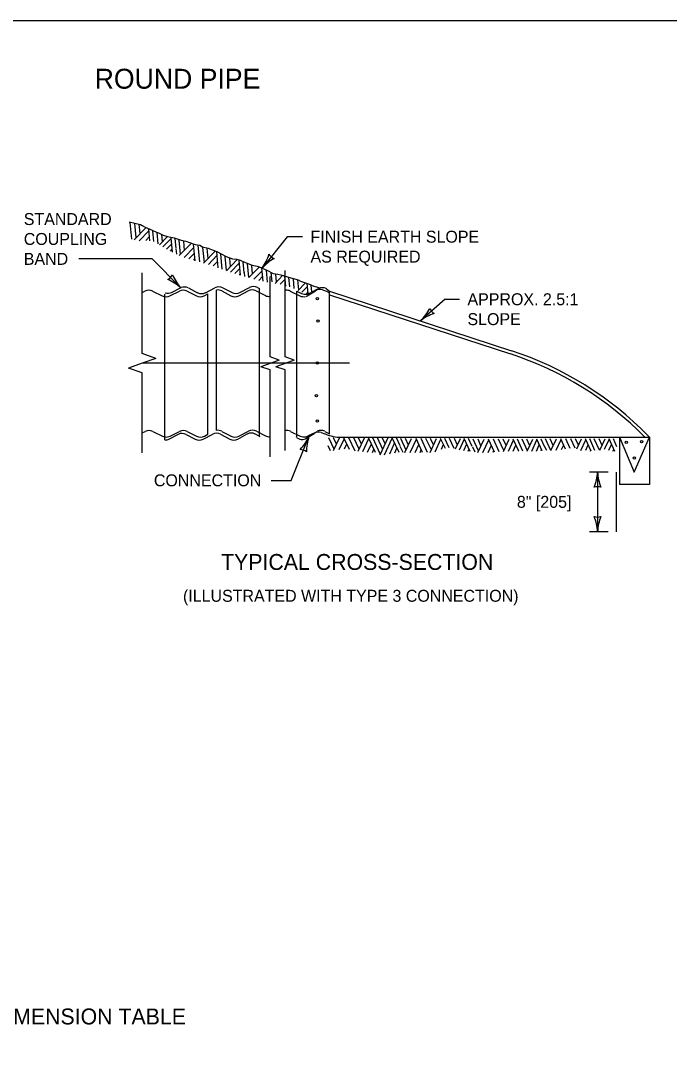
# Model space of a CAD drawing. Extents: x 49991.4 to 50021, y 49987.6 to 50011.4.
# Drawn here: x 50010.14 to 50013.4, y 49993.85 to 49999 of the extents above; entities that cross this region are included whole.
import ezdxf

# ---------------------------------------------------------------- set-up
doc = ezdxf.new("R2010")
doc.units = 0
for name, color, linetype in [('Level 1', 7, 'Continuous'), ('Level 2', 7, 'Continuous'), ('Level 3', 7, 'Continuous'), ('Level 4', 7, 'Continuous'), ('Level 5', 7, 'Continuous'), ('Level 6', 7, 'Continuous')]:
    doc.layers.add(name, color=color, linetype=linetype)

msp = doc.modelspace()

# ---------------------------------------------------------------- linework, layer by layer
at = {"layer": 'Level 1'}
for p, q in [((50010.7033, 49997.9015), (50010.6957, 49997.9852)), ((50010.7251, 49997.9089), (50010.719, 49997.9791)), ((50010.7446, 49997.9285), (50010.7405, 49997.9755)), ((50010.7149, 49997.8973), (50010.7753, 49997.9596)), ((50010.7405, 49997.8927), (50010.7891, 49997.9422)), ((50010.7744, 49997.8948), (50010.792, 49997.9137)), ((50010.7941, 49997.8916), (50010.7884, 49997.9522)), ((50010.8138, 49997.8885), (50010.8089, 49997.9428)), ((50010.836, 49997.8769), (50010.8307, 49997.9338)), ((50010.8418, 49997.8726), (50010.8826, 49997.9144)), ((50010.857, 49997.8886), (50010.854, 49997.9245)), ((50010.8583, 49997.8617), (50010.9006, 49997.9049)), ((50010.8782, 49997.8509), (50010.9038, 49997.8774)), ((50010.9076, 49997.836), (50010.9004, 49997.9079)), ((50010.9253, 49997.8561), (50010.9207, 49997.9036)), ((50010.9483, 49997.825), (50010.941, 49997.8963)), ((50010.9418, 49997.8181), (50011.0016, 49997.8796)), ((50010.9674, 49997.8444), (50010.9638, 49997.8906)), ((50010.9658, 49997.8093), (50011.0149, 49997.8594)), ((50011.0213, 49997.7925), (50011.0128, 49997.8759)), ((50011.0446, 49997.7863), (50011.0364, 49997.8694)), ((50011.0676, 49997.7839), (50011.0604, 49997.8587)), ((50010.8977, 49997.8413), (50010.9058, 49997.8503)), ((50010.9286, 49997.825), (50010.9262, 49997.852)), ((50010.9895, 49997.8013), (50011.0178, 49997.8299)), ((50011.064, 49997.7808), (50011.1226, 49997.8403)), ((50011.0867, 49997.8043), (50011.0821, 49997.8532)), ((50011.0876, 49997.7736), (50011.1308, 49997.8179)), ((50011.1372, 49997.7572), (50011.1294, 49997.8375)), ((50011.1572, 49997.7503), (50011.1498, 49997.8255)), ((50011.1792, 49997.7428), (50011.1721, 49997.8138)), ((50011.0141, 49997.7947), (50011.0202, 49997.8013)), ((50011.1121, 49997.7661), (50011.1341, 49997.789)), ((50011.1359, 49997.7578), (50011.1373, 49997.7595)), ((50011.1787, 49997.7425), (50011.2325, 49997.798)), ((50011.1995, 49997.7637), (50011.1953, 49997.8035)), ((50011.1991, 49997.7353), (50011.2428, 49997.7805)), ((50011.2487, 49997.7194), (50011.242, 49997.794)), ((50011.267, 49997.732), (50011.2625, 49997.7866)), ((50011.2909, 49997.7074), (50011.2838, 49997.7785)), ((50011.2909, 49997.7074), (50011.342, 49997.7601)), ((50011.3101, 49997.7274), (50011.3065, 49997.7688)), ((50011.3623, 49997.6897), (50011.3559, 49997.7557)), ((50011.2211, 49997.7278), (50011.2451, 49997.7529)), ((50011.244, 49997.7206), (50011.2478, 49997.7256)), ((50011.2711, 49997.7129), (50011.269, 49997.7334)), ((50011.3167, 49997.6999), (50011.3573, 49997.7417)), ((50011.3419, 49997.6939), (50011.3603, 49997.7125)), ((50011.3855, 49997.6852), (50011.3797, 49997.7447)), ((50011.4082, 49997.6865), (50011.4035, 49997.7333)), ((50011.4227, 49997.6787), (50011.4602, 49997.7178)), ((50011.4292, 49997.6865), (50011.4257, 49997.7247)), ((50011.4773, 49997.6655), (50011.4721, 49997.7145)), ((50011.497, 49997.6606), (50011.4924, 49997.7076)), ((50010.903, 49997.6337), (50010.9508, 49997.6572)), ((50010.9871, 49997.6555), (50011.0336, 49997.6319)), ((50011.0728, 49997.6319), (50011.1206, 49997.6567)), ((50011.1602, 49997.6565), (50011.2064, 49997.6324)), ((50011.2464, 49997.6324), (50011.2942, 49997.6575)), ((50011.3344, 49997.6575), (50011.3441, 49997.6524)), ((50011.448, 49997.6739), (50011.4738, 49997.7001)), ((50011.5193, 49997.6527), (50011.5145, 49997.7017)), ((50011.5417, 49997.6462), (50011.5373, 49997.6968)), ((50011.5385, 49997.6429), (50011.5746, 49997.6803)), ((50011.5579, 49997.6347), (50011.5854, 49997.6629)), ((50011.5884, 49997.6296), (50011.5842, 49997.6776)), ((50011.6075, 49997.6387), (50011.6046, 49997.6685)), ((50011.605, 49997.6345), (50011.6407, 49997.6524)), ((50011.6304, 49997.6613), (50011.6437, 49997.656)), ((50011.6797, 49997.6524), (50011.6965, 49997.639)), ((50010.7546, 49997.6324), (50010.7692, 49997.6396)), ((50010.8079, 49997.6399), (50010.8564, 49997.6158)), ((50010.8943, 49997.6158), (50010.9422, 49997.6396)), ((50010.9814, 49997.6395), (50011.0273, 49997.6158)), ((50011.0668, 49997.6158), (50011.0852, 49997.6255)), ((50011.0852, 49996.9207), (50011.0852, 49997.6255)), ((50011.1284, 49996.9403), (50011.1284, 49997.6451)), ((50011.1545, 49997.6408), (50011.2007, 49997.6164)), ((50011.2406, 49997.6164), (50011.2883, 49997.6416)), ((50011.3282, 49997.6416), (50011.374, 49997.6176)), ((50011.4785, 49997.6449), (50011.4726, 49997.6439)), ((50011.4989, 49997.6402), (50011.5469, 49997.6162)), ((50011.5321, 49996.9041), (50011.5321, 49997.6395)), ((50011.5321, 49997.6395), (50011.5547, 49997.6284)), ((50011.5813, 49997.6285), (50011.588, 49997.6353)), ((50011.5842, 49997.6158), (50011.6262, 49997.642)), ((50011.5931, 49997.6284), (50011.6045, 49997.6337)), ((50011.6603, 49997.6467), (50011.6804, 49997.639)), ((50011.6804, 49997.639), (50011.6964, 49997.6315)), ((50011.6964, 49997.6393), (50012.6098, 49997.3402)), ((50011.6964, 49997.6219), (50012.6047, 49997.3245)), ((50010.7552, 49996.9277), (50010.77, 49996.9351)), ((50010.809, 49996.9351), (50010.8569, 49996.9111)), ((50010.8956, 49996.9112), (50010.9428, 49996.9351)), ((50010.9819, 49996.9346), (50011.0279, 49996.9111)), ((50011.1557, 49996.9354), (50011.2014, 49996.9115)), ((50011.2415, 49996.9115), (50011.2894, 49996.9367)), ((50011.3291, 49996.9369), (50011.3748, 49996.913)), ((50011.4994, 49996.9354), (50011.5482, 49996.9115)), ((50011.5985, 49996.9175), (50011.634, 49996.9354)), ((50011.6538, 49996.9303), (50011.6734, 49996.9222)), ((50011.6728, 49996.9354), (50011.6965, 49996.9235)), ((50010.8677, 49996.8952), (50010.8691, 49996.8952)), ((50010.889, 49996.8965), (50010.937, 49996.9205)), ((50010.9754, 49996.9201), (50011.022, 49996.8965)), ((50011.0614, 49996.8965), (50011.1096, 49996.9213)), ((50011.0677, 49996.9112), (50011.0852, 49996.9205)), ((50011.1492, 49996.9209), (50011.195, 49996.8967)), ((50011.2352, 49996.8967), (50011.2828, 49996.9221)), ((50011.3228, 49996.9221), (50011.3454, 49996.9103)), ((50011.5302, 49996.9065), (50011.5302, 49996.9072)), ((50011.5321, 49996.9034), (50011.5405, 49996.8993)), ((50011.5774, 49996.8991), (50011.6194, 49996.9252)), ((50011.5862, 49996.9115), (50011.5975, 49996.9171)), ((50011.7193, 49996.8453), (50011.692, 49996.9034)), ((50011.7312, 49996.8705), (50011.7158, 49996.9034)), ((50011.7168, 49996.8395), (50011.7462, 49996.9034)), ((50011.7445, 49996.8436), (50011.7706, 49996.8998)), ((50011.7562, 49996.9063), (50013.3036, 49996.9063)), ((50011.7961, 49996.8448), (50011.7686, 49996.9034)), ((50011.8248, 49996.8364), (50011.7937, 49996.9034)), ((50011.8454, 49996.846), (50011.8189, 49996.9034)), ((50011.8402, 49996.8351), (50011.8721, 49996.9034)), ((50011.8566, 49996.8715), (50011.8417, 49996.9034)), ((50011.8634, 49996.8334), (50011.8939, 49996.8993)), ((50011.9274, 49996.8285), (50011.8922, 49996.9034)), ((50011.9525, 49996.8196), (50011.9134, 49996.9034)), ((50011.9641, 49996.8448), (50011.9369, 49996.9034)), ((50011.9512, 49996.8169), (50011.9915, 49996.904)), ((50011.9765, 49996.8705), (50011.9612, 49996.9034)), ((50011.9729, 49996.8172), (50012.0116, 49996.901)), ((50012.0456, 49996.8285), (50012.0112, 49996.9034)), ((50012.0512, 49996.8633), (50012.0325, 49996.9034)), ((50012.0817, 49996.8413), (50012.0542, 49996.8998)), ((50012.0752, 49996.8285), (50012.1081, 49996.8998)), ((50012.0931, 49996.8667), (50012.078, 49996.8998)), ((50012.1014, 49996.8285), (50012.1327, 49996.8959)), ((50012.1638, 49996.8285), (50012.1308, 49996.8998)), ((50012.1888, 49996.8285), (50012.1558, 49996.8998)), ((50012.2076, 49996.8423), (50012.1807, 49996.8998)), ((50012.2008, 49996.8285), (50012.2341, 49996.8998)), ((50012.2183, 49996.8677), (50012.204, 49996.8998)), ((50012.2269, 49996.8321), (50012.256, 49996.8953)), ((50012.278, 49996.8493), (50012.2542, 49996.8998)), ((50012.2975, 49996.8524), (50012.2754, 49996.8998)), ((50012.3222, 49996.8493), (50012.299, 49996.8998)), ((50012.3382, 49996.8668), (50012.3232, 49996.8998)), ((50012.329, 49996.8472), (50012.3535, 49996.9001)), ((50012.3485, 49996.8423), (50012.3737, 49996.8973)), ((50012.4032, 49996.8344), (50012.3727, 49996.8998)), ((50012.413, 49996.8593), (50012.3943, 49996.8998)), ((50012.4452, 49996.8376), (50012.4181, 49996.8959)), ((50012.441, 49996.8287), (50012.4723, 49996.8959)), ((50012.4568, 49996.8626), (50012.4422, 49996.8959)), ((50012.4669, 49996.8285), (50012.4968, 49996.892)), ((50012.5249, 49996.8313), (50012.4945, 49996.8959)), ((50012.5488, 49996.8331), (50012.5198, 49996.8959)), ((50012.5714, 49996.8385), (50012.5448, 49996.8959)), ((50012.5826, 49996.8638), (50012.5682, 49996.8959)), ((50012.5694, 49996.8344), (50012.5978, 49996.8959)), ((50012.5945, 49996.8352), (50012.6203, 49996.8914)), ((50012.6464, 49996.8362), (50012.6182, 49996.8959)), ((50012.6673, 49996.8362), (50012.6395, 49996.8959)), ((50012.6902, 49996.837), (50012.6632, 49996.8959)), ((50012.7024, 49996.8626), (50012.6874, 49996.8959)), ((50012.6895, 49996.8362), (50012.7172, 49996.8962)), ((50012.7114, 49996.8362), (50012.7375, 49996.8933)), ((50012.7638, 49996.8376), (50012.7368, 49996.8959)), ((50012.7774, 49996.8554), (50012.7586, 49996.8959)), ((50012.8084, 49996.8395), (50012.781, 49996.8976)), ((50012.8201, 49996.8649), (50012.805, 49996.8976)), ((50012.8084, 49996.8395), (50012.8356, 49996.8976)), ((50012.8348, 49996.841), (50012.8594, 49996.8938)), ((50012.8816, 49996.8465), (50012.8579, 49996.8976)), ((50012.9052, 49996.8497), (50012.8827, 49996.8976)), ((50012.93, 49996.8501), (50012.908, 49996.8976)), ((50012.9458, 49996.8657), (50012.9312, 49996.8976)), ((50012.9379, 49996.8477), (50012.9611, 49996.8976)), ((50012.958, 49996.8395), (50012.983, 49996.8935)), ((50013.0105, 49996.8355), (50012.9814, 49996.8976)), ((50013.0294, 49996.8395), (50013.0027, 49996.8976)), ((50013.052, 49996.841), (50013.026, 49996.8976)), ((50013.0657, 49996.8649), (50013.0502, 49996.8976)), ((50013.0542, 49996.841), (50013.0805, 49996.898)), ((50013.0776, 49996.8453), (50013.1008, 49996.8951)), ((50013.1296, 49996.8345), (50013.1, 49996.8976)), ((50013.1399, 49996.8575), (50013.1218, 49996.8976)), ((50013.1527, 49996.9063), (50013.1527, 49996.6689)), ((50013.1527, 49996.9063), (50013.2259, 49996.7309)), ((50013.2259, 49996.7309), (50013.3037, 49996.9063)), ((50013.3036, 49996.9058), (50013.2955, 49996.9142)), ((50013.3037, 49996.9063), (50013.3037, 49996.6689)), ((50011.7013, 49996.8376), (50011.6894, 49996.8633)), ((50011.771, 49996.8476), (50011.783, 49996.8731)), ((50011.7946, 49996.8453), (50011.7955, 49996.8466)), ((50011.8873, 49996.8315), (50011.9066, 49996.8731)), ((50011.9117, 49996.8299), (50011.9191, 49996.8459)), ((50011.999, 49996.8223), (50012.0233, 49996.8758)), ((50012.0247, 49996.8274), (50012.035, 49996.8511)), ((50012.0659, 49996.8285), (50012.0514, 49996.8593)), ((50012.1261, 49996.8285), (50012.1448, 49996.8689)), ((50012.1506, 49996.8285), (50012.157, 49996.843)), ((50012.2578, 49996.8458), (50012.2686, 49996.8689)), ((50012.3708, 49996.8391), (50012.3854, 49996.8719)), ((50012.392, 49996.8361), (50012.3972, 49996.8475)), ((50012.4268, 49996.8307), (50012.4152, 49996.8554)), ((50012.4922, 49996.8287), (50012.5089, 49996.8655)), ((50012.5176, 49996.8307), (50012.521, 49996.8391)), ((50012.6192, 49996.8362), (50012.6326, 49996.8655)), ((50012.6442, 49996.8362), (50012.6452, 49996.838)), ((50012.7352, 49996.8362), (50012.7498, 49996.8683)), ((50012.7586, 49996.8373), (50012.7613, 49996.8434)), ((50012.7872, 49996.8386), (50012.7783, 49996.8575)), ((50012.8609, 49996.8439), (50012.8723, 49996.8674)), ((50012.9828, 49996.8403), (50012.9955, 49996.8674)), ((50013.0067, 49996.8362), (50013.0085, 49996.8403)), ((50013.0992, 49996.8412), (50013.1124, 49996.87)), ((50013.1198, 49996.8355), (50013.1239, 49996.8453)), ((50013.3037, 49996.6689), (50013.1527, 49996.6689))]:
    msp.add_line(p, q, dxfattribs=at)
msp.add_lwpolyline([(49999.3835, 49998.9992), (50016.7501, 49998.9992), (50016.7501, 49987.7988), (49999.3835, 49987.7988)], close=True, dxfattribs=at)
for points in [[(50010.69, 49997.9878), (50010.7467, 49997.9745), (50010.755, 49997.9696), (50010.77, 49997.9613), (50010.7934, 49997.9512), (50010.805, 49997.9464), (50010.8269, 49997.9363), (50010.8368, 49997.9329), (50010.8601, 49997.9212), (50010.8818, 49997.9147), (50010.9152, 49997.908), (50010.9268, 49997.9048), (50010.9518, 49997.8964), (50010.9738, 49997.8899), (50010.9937, 49997.8832), (50011.022, 49997.8748), (50011.0454, 49997.8699), (50011.0587, 49997.8615), (50011.0872, 49997.8549), (50011.1121, 49997.845), (50011.1306, 49997.8383), (50011.1521, 49997.8267), (50011.1772, 49997.8133), (50011.209, 49997.8017), (50011.2304, 49997.8), (50011.2472, 49997.795), (50011.2688, 49997.785), (50011.2771, 49997.7819)], [(50011.2768, 49997.7827), (50011.3083, 49997.771), (50011.3334, 49997.7644), (50011.3435, 49997.761), (50011.3819, 49997.7443), (50011.4134, 49997.7278), (50011.4368, 49997.7244), (50011.4518, 49997.7212), (50011.5019, 49997.7062), (50011.5387, 49997.6961), (50011.5504, 49997.6895), (50011.5903, 49997.6763), (50011.6171, 49997.6647), (50011.6304, 49997.6613)], [(50011.643, 49997.656), (50011.6406, 49997.6581)]]:
    msp.add_lwpolyline(points, dxfattribs=at)
for centre, radius in [((50011.635, 49997.6019), 0.00595), ((50011.6386, 49997.4893), 0.00595), ((50011.635, 49997.2786), 0.00595), ((50011.63, 49997.1146), 0.00595), ((50011.635, 49996.9871), 0.00595), ((50013.1862, 49996.8799), 0.00594), ((50013.2632, 49996.8829), 0.00594), ((50013.2274, 49996.8009), 0.00594)]:
    msp.add_circle(centre, radius, dxfattribs=at)
for centre, radius, start, end in [((50010.9674, 49997.6173), 0.0432, 62.9182, 112.5905), ((50011.1404, 49997.6184), 0.0432, 62.3296, 117.1813), ((50011.3142, 49997.6193), 0.0432, 62.5543, 117.6538), ((50011.6602, 49997.6138), 0.0432, 63.1956, 116.6972), ((50010.7888, 49997.6013), 0.0432, 63.5216, 116.8449), ((50010.8754, 49997.6546), 0.0432, 243.5224, 296.6032), ((50010.8836, 49997.6722), 0.0432, 251.8711, 296.6032), ((50010.9615, 49997.6013), 0.0432, 62.9182, 116.6003), ((50011.0471, 49997.6544), 0.0432, 242.9112, 297.1838), ((50011.0529, 49997.6705), 0.0432, 242.9112, 297.1838), ((50011.1346, 49997.6023), 0.0432, 62.3296, 98.166), ((50011.2206, 49997.6547), 0.0432, 242.3292, 297.6433), ((50011.2265, 49997.6708), 0.0432, 242.3292, 297.6433), ((50011.3084, 49997.6032), 0.0432, 62.5543, 117.6538), ((50011.3939, 49997.656), 0.0432, 242.558, 274.6236), ((50011.4795, 49997.6016), 0.0432, 63.6272, 91.014), ((50011.5663, 49997.655), 0.0432, 243.619, 283.116), ((50011.5738, 49997.667), 0.0432, 243.619, 283.116), ((50011.5663, 49997.655), 0.0432, 286.7943, 296.2055), ((50011.5738, 49997.667), 0.0432, 286.7943, 296.6877), ((50011.6492, 49997.6053), 0.0432, 74.5382, 121.9141), ((50011.6962, 49997.6388), 0.000671, 66.5628, 330.1508), ((50012.0811, 49995.7246), 1.6834, 44.5892, 71.8806), ((50012.0811, 49995.7246), 1.7, 44.4117, 71.8806), ((50010.7896, 49996.8965), 0.0432, 63.5216, 116.8449), ((50010.9623, 49996.8965), 0.0432, 62.9182, 116.6003), ((50011.1354, 49996.8976), 0.0432, 62.3296, 99.3453), ((50011.3092, 49996.8984), 0.0432, 62.5543, 117.6538), ((50011.4803, 49996.8968), 0.0432, 63.6272, 101.0088), ((50011.6424, 49996.8885), 0.0432, 74.5382, 121.9141), ((50011.6534, 49996.897), 0.0432, 63.1956, 116.6972), ((50010.8762, 49996.9499), 0.0432, 243.5224, 261.4108), ((50010.8762, 49996.9499), 0.0432, 261.7501, 296.6032), ((50010.87, 49996.9351), 0.0432, 271.3626, 296.6032), ((50010.9561, 49996.8817), 0.0432, 62.9182, 116.6003), ((50011.0417, 49996.9349), 0.0432, 242.9112, 297.1838), ((50011.0479, 49996.9497), 0.0432, 242.9112, 297.1838), ((50011.1292, 49996.8828), 0.0432, 62.3296, 117.1813), ((50011.2152, 49996.9351), 0.0432, 242.3292, 297.6433), ((50011.2214, 49996.9499), 0.0432, 242.3292, 297.6433), ((50011.303, 49996.8837), 0.0432, 62.5543, 117.6538), ((50011.3947, 49996.9512), 0.0432, 242.558, 272.8099), ((50011.5595, 49996.9381), 0.0432, 243.619, 283.116), ((50011.5671, 49996.9502), 0.0432, 243.619, 283.116), ((50011.5595, 49996.9381), 0.0432, 286.7943, 296.2055), ((50011.5671, 49996.9502), 0.0432, 286.7943, 296.6877), ((50011.7563, 49997.1216), 0.2158, 247.5327, 270)]:
    msp.add_arc(centre, radius, start, end, dxfattribs=at)
at = {"layer": 'Level 3'}
for p, q in [((50011.483, 49997.9131), (50011.3579, 49997.7548)), ((50011.5606, 49997.9131), (50011.483, 49997.9131)), ((50010.8053, 49997.8018), (50010.4365, 49997.8018)), ((50010.8053, 49997.8018), (50010.9488, 49997.6562)), ((50012.2768, 49997.599), (50012.1532, 49997.4898)), ((50012.2768, 49997.599), (50012.349, 49997.599)), ((50011.5041, 49996.6893), (50011.593, 49996.9088)), ((50013.0954, 49996.7309), (50013.0022, 49996.7309)), ((50013.0422, 49996.7309), (50013.0422, 49996.4314)), ((50011.4036, 49996.6893), (50011.5041, 49996.6893)), ((50013.0954, 49996.4314), (50013.0022, 49996.4314))]:
    msp.add_line(p, q, dxfattribs=at)
for centre, radius, start, end in [((50011.1682, 49997.8901), 0.233, 324.496, 343.7459), ((50011.4374, 49997.8554), 0.0548, 213.8076, 249.5299), ((50011.5264, 49997.6099), 0.2223, 119.1247, 139.3083), ((50010.8588, 49997.7475), 0.0548, 296.7069, 332.4292), ((50011.1135, 49997.8056), 0.2223, 202.024, 222.2075), ((50010.7911, 49997.4847), 0.233, 47.3953, 66.6452), ((50011.9905, 49997.6566), 0.233, 314.2908, 333.5406), ((50012.2493, 49997.5747), 0.0548, 203.6023, 239.3247), ((50012.2934, 49997.3173), 0.2223, 108.9195, 129.103), ((50011.3906, 49997.0007), 0.2223, 315.4075, 335.591), ((50011.813, 49996.8321), 0.233, 160.7788, 180.0287), ((50011.5449, 49996.79), 0.0548, 50.0903, 85.8127), ((50012.8201, 49996.7401), 0.2223, 337.456, 357.6395), ((50013.275, 49996.7424), 0.233, 182.8273, 202.0772), ((50013.0422, 49996.6027), 0.0548, 72.1388, 107.8612), ((50013.0422, 49996.5597), 0.0548, 252.1388, 287.8612), ((50012.8095, 49996.42), 0.233, 2.8273, 22.0772), ((50013.2644, 49996.4223), 0.2223, 157.456, 177.6395)]:
    msp.add_arc(centre, radius, start, end, dxfattribs=at)
at = {"layer": 'Level 4'}
for p, q in [((50011.3446, 49996.9149), (50011.3446, 49997.6525)), ((50010.8696, 49996.892), (50010.8696, 49997.6251)), ((50011.6964, 49996.9236), (50011.6964, 49997.6395)), ((50011.6964, 49997.4311), (50011.6964, 49997.4325)), ((50011.6964, 49997.122), (50011.6964, 49997.1227)), ((50013.1354, 49996.7309), (50013.1354, 49996.4314))]:
    msp.add_line(p, q, dxfattribs=at)
at = {"layer": 'Level 5'}
msp.add_line((50011.7964, 49997.2774), (50010.7546, 49997.2774), dxfattribs=at)
at = {"layer": 'Level 6'}
for p, q in [((50010.7546, 49997.326), (50010.7546, 49997.7324)), ((50011.3973, 49997.3089), (50011.3973, 49997.713)), ((50011.4726, 49997.3089), (50011.4726, 49997.7439)), ((50010.8231, 49997.3017), (50010.7546, 49997.326)), ((50010.8231, 49997.3017), (50010.7546, 49997.2774)), ((50011.443, 49997.2927), (50011.3973, 49997.3089)), ((50011.443, 49997.2927), (50011.3973, 49997.2765)), ((50011.5183, 49997.2927), (50011.4726, 49997.3089)), ((50011.5183, 49997.2927), (50011.4726, 49997.2765)), ((50010.7546, 49997.2774), (50010.6861, 49997.2531)), ((50010.7546, 49997.2288), (50010.6861, 49997.2531)), ((50011.3973, 49997.2765), (50011.3516, 49997.2603)), ((50011.3973, 49997.2441), (50011.3516, 49997.2603)), ((50011.3973, 49996.8082), (50011.3973, 49997.2441)), ((50011.4726, 49997.2765), (50011.4269, 49997.2603)), ((50011.4726, 49997.2441), (50011.4269, 49997.2603)), ((50011.4726, 49996.8393), (50011.4726, 49997.2441)), ((50010.7546, 49996.8274), (50010.7546, 49997.2288))]:
    msp.add_line(p, q, dxfattribs=at)

# ---------------------------------------------------------------- texts
at = {"layer": 'Level 2'}
for s, height, p in [('ROUND PIPE', 0.1, (50010.5166, 49998.6567)), ('STANDARD', 0.06, (50010.1607, 49997.9718)), ('COUPLING', 0.06, (50010.1607, 49997.8718)), ('FINISH EARTH SLOPE', 0.06, (50011.6006, 49997.8831)), ('BAND', 0.06, (50010.1607, 49997.7718)), ('AS REQUIRED', 0.06, (50011.6006, 49997.7831)), ('APPROX. 2.5:1', 0.06, (50012.389, 49997.569)), ('SLOPE', 0.06, (50012.389, 49997.469)), ('CONNECTION', 0.06, (50010.8141, 49996.6593)), ('8" [205]', 0.06, (50012.6373, 49996.5512)), ('TYPICAL CROSS-SECTION', 0.08, (50011.1514, 49996.2393)), ('(ILLUSTRATED WITH TYPE 3 CONNECTION)', 0.06, (50010.9603, 49996.0793)), ('DIMENSION TABLE', 0.08, (50010.0003, 49993.9561))]:
    msp.add_text(s, height=height, dxfattribs=at).set_placement(p)

doc.saveas('drawing.dxf')
